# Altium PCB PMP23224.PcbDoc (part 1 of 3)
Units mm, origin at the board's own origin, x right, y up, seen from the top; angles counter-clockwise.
Board outline 180 x 75 mm, 4 copper layers (Top Layer, Signal Layer 1, Signal Layer 2, Bottom Layer), stack 1.565 mm thick; 189 components, 98 nets, 443 pads, 89 vias.
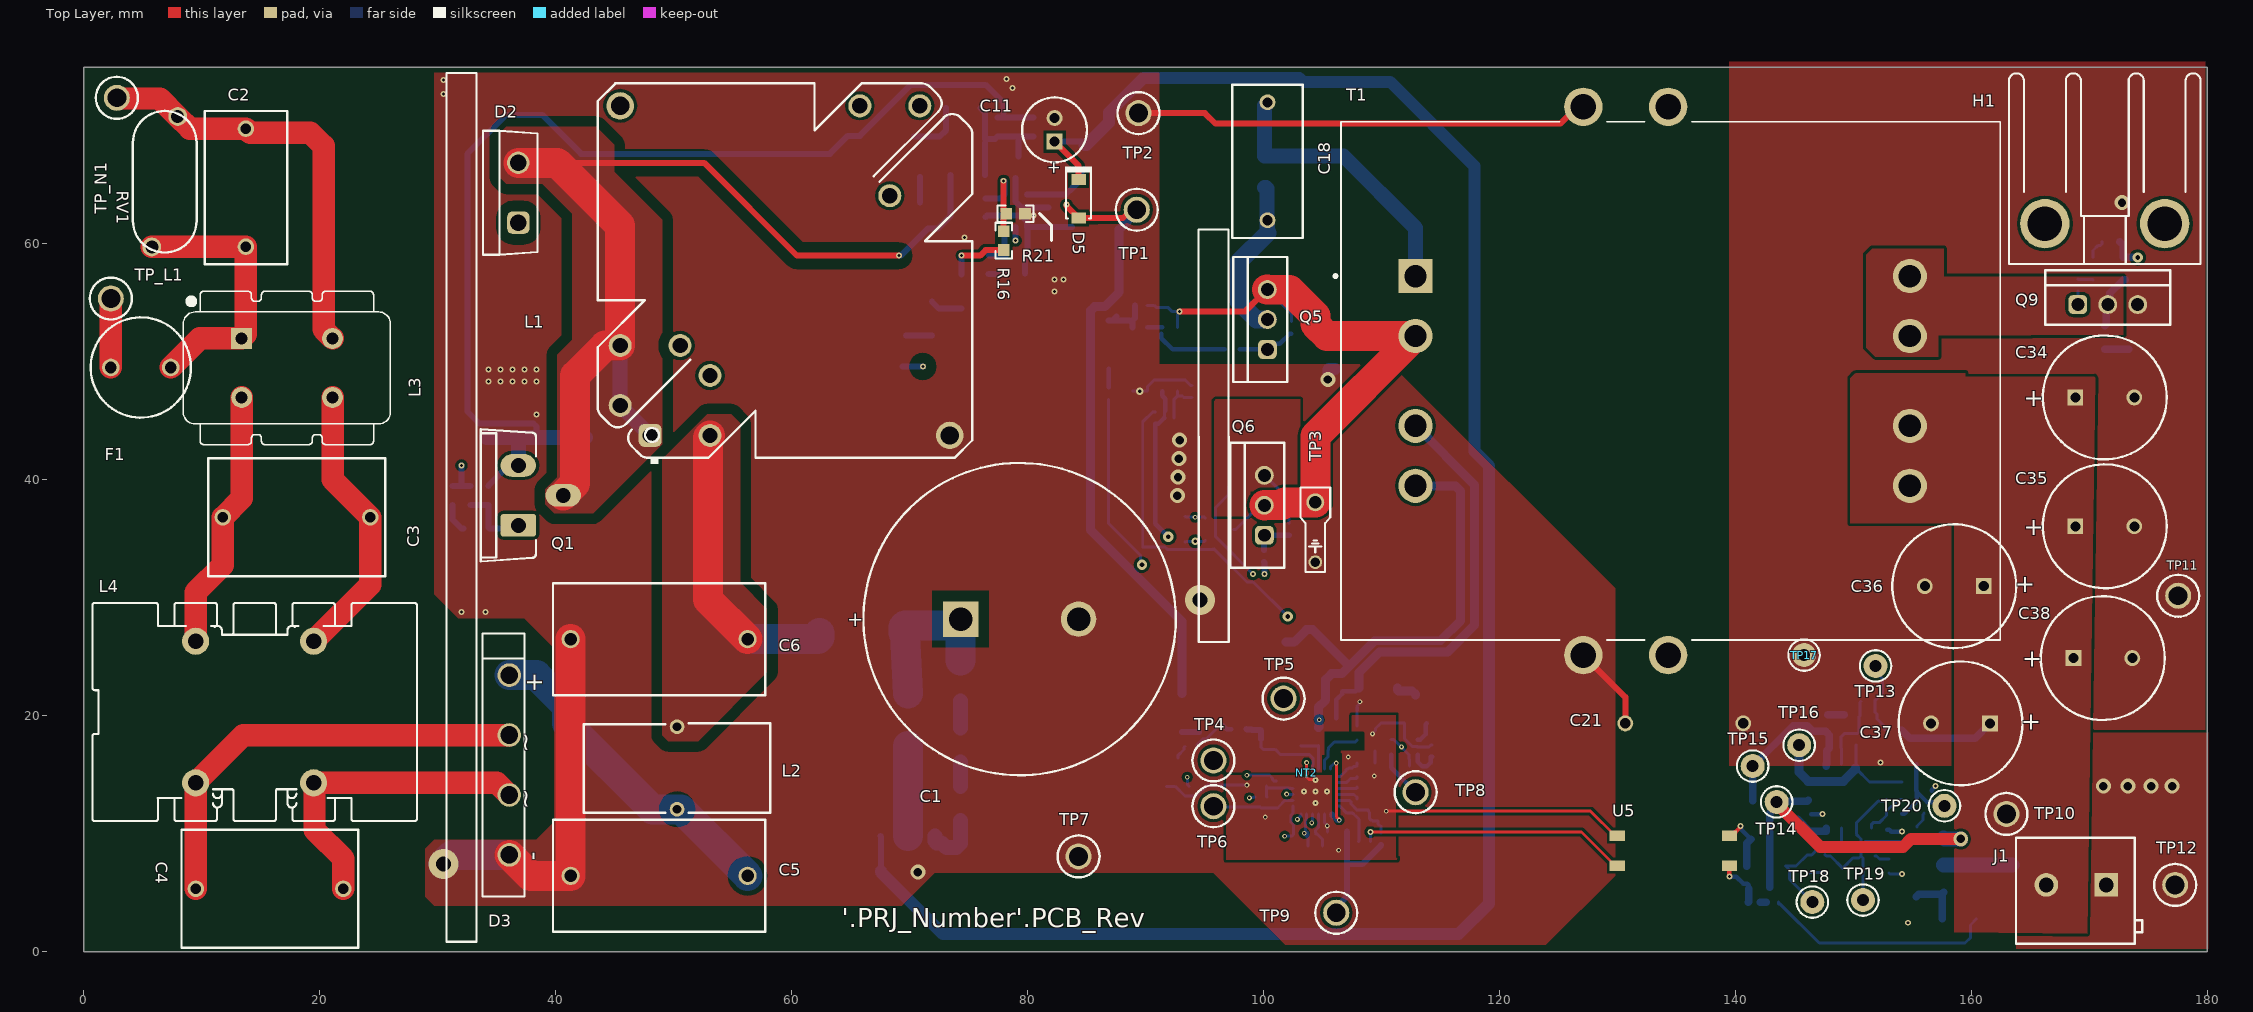
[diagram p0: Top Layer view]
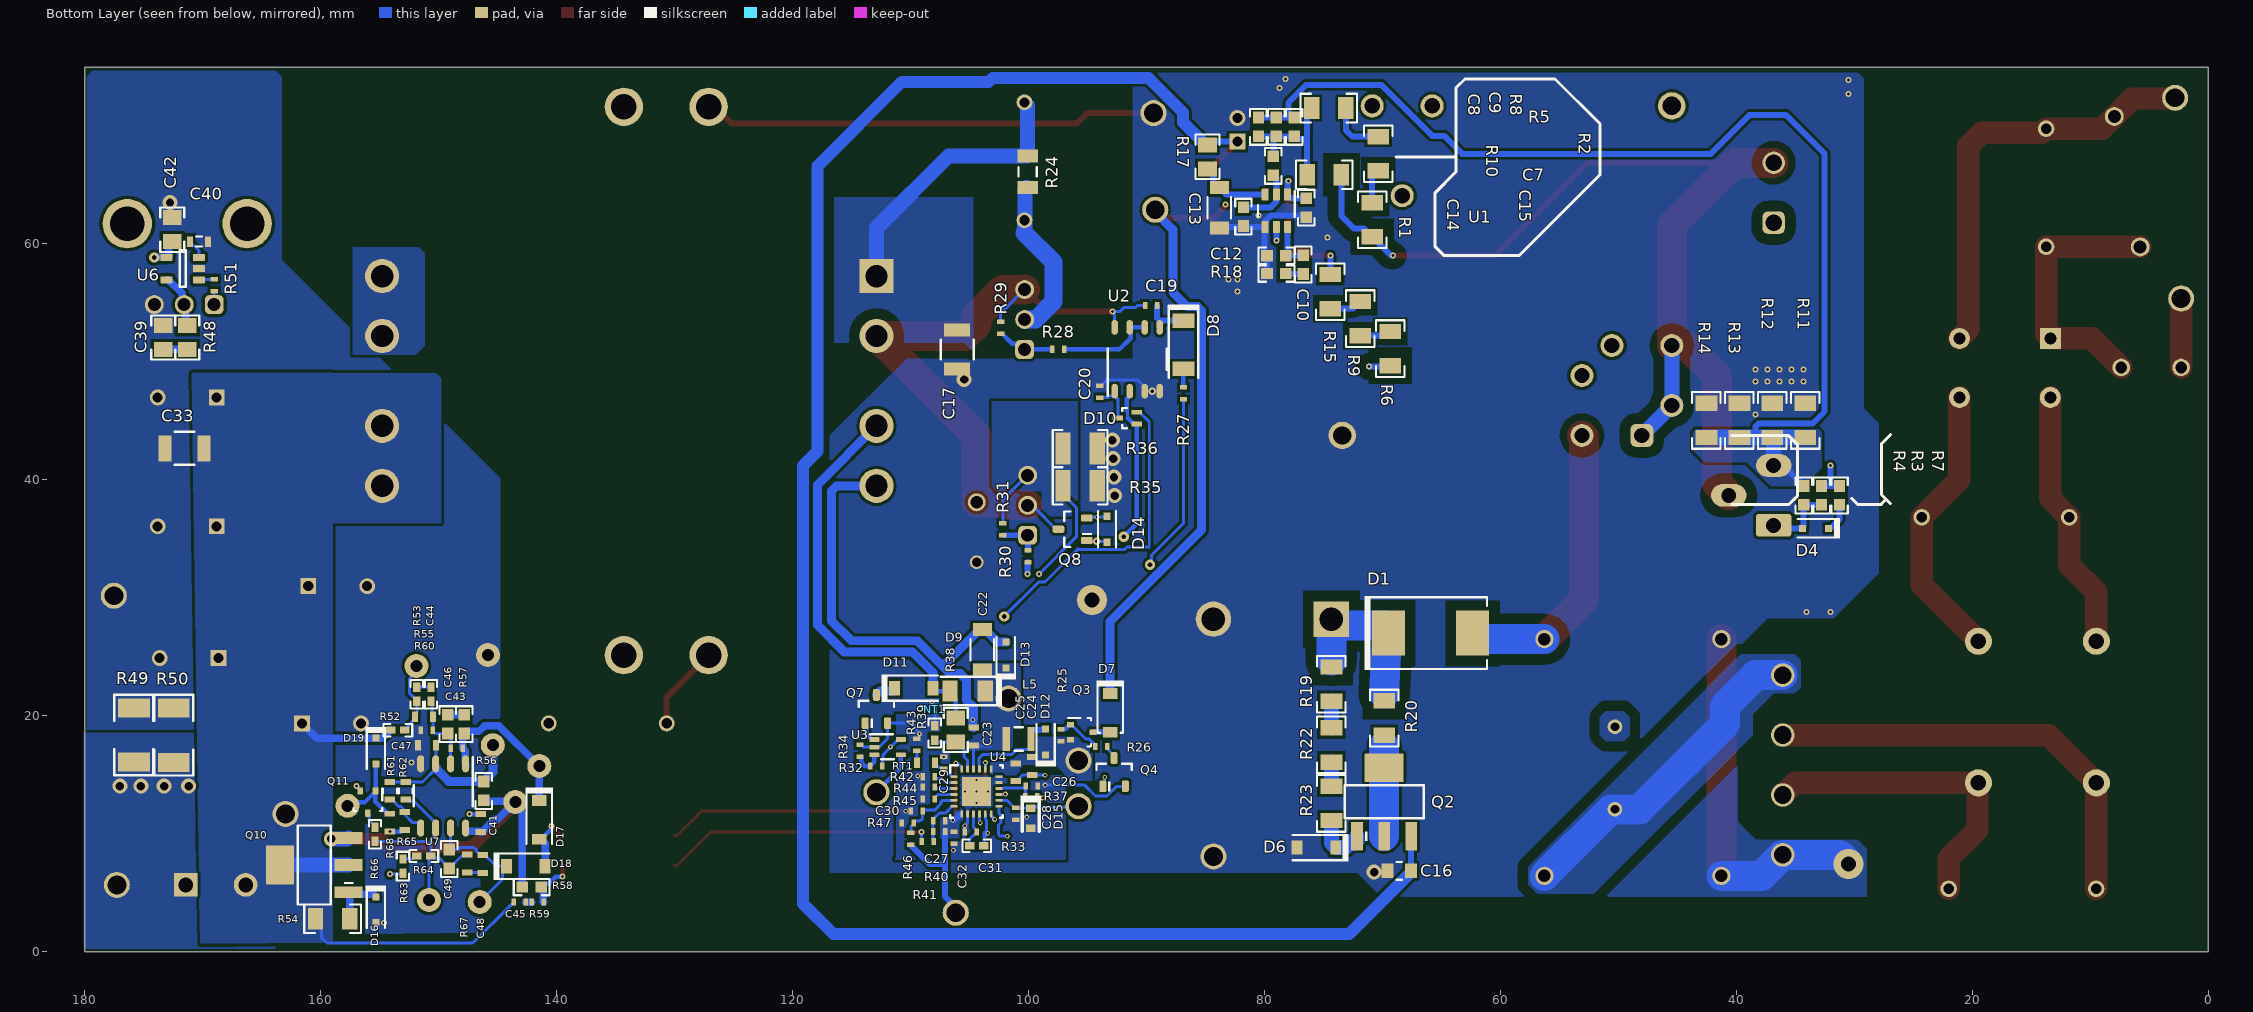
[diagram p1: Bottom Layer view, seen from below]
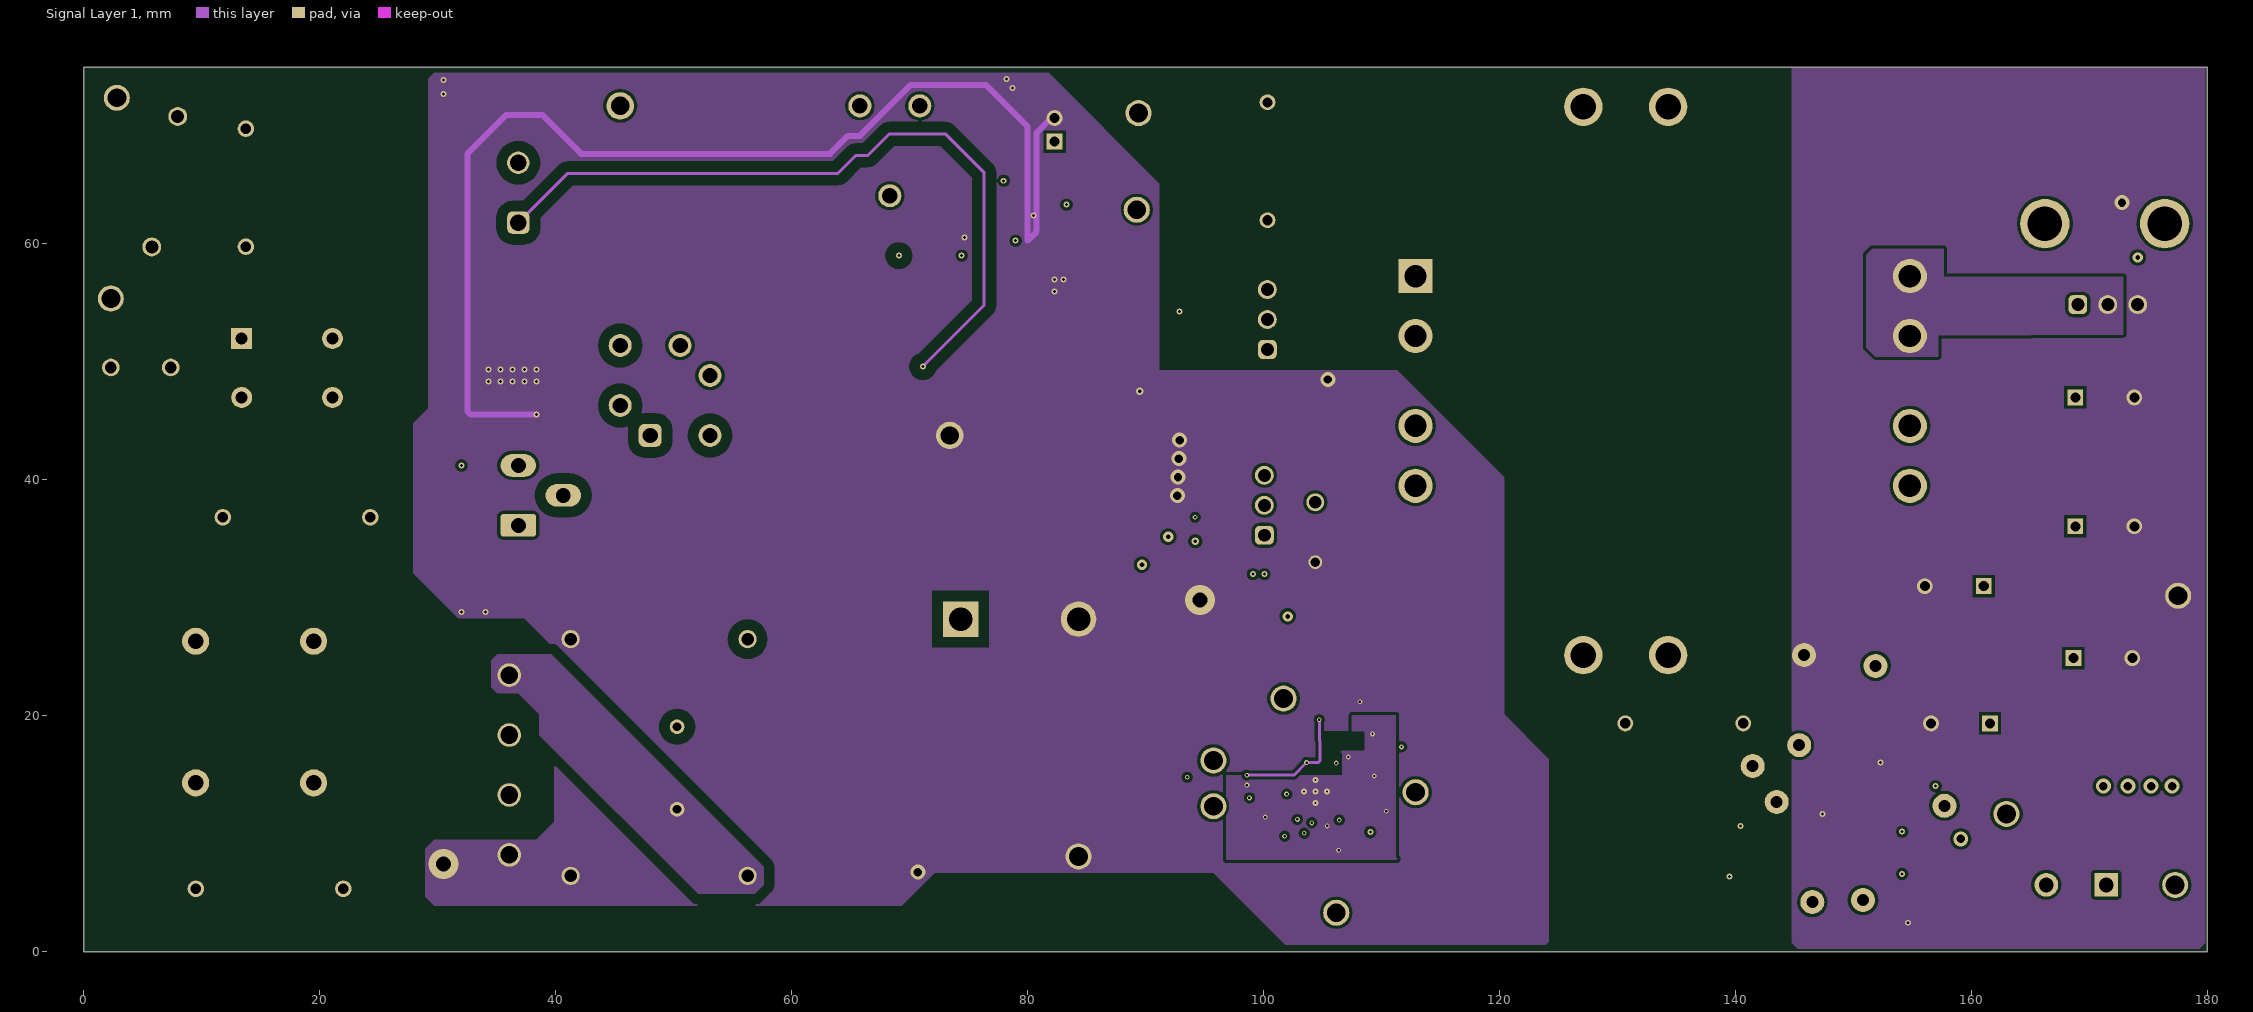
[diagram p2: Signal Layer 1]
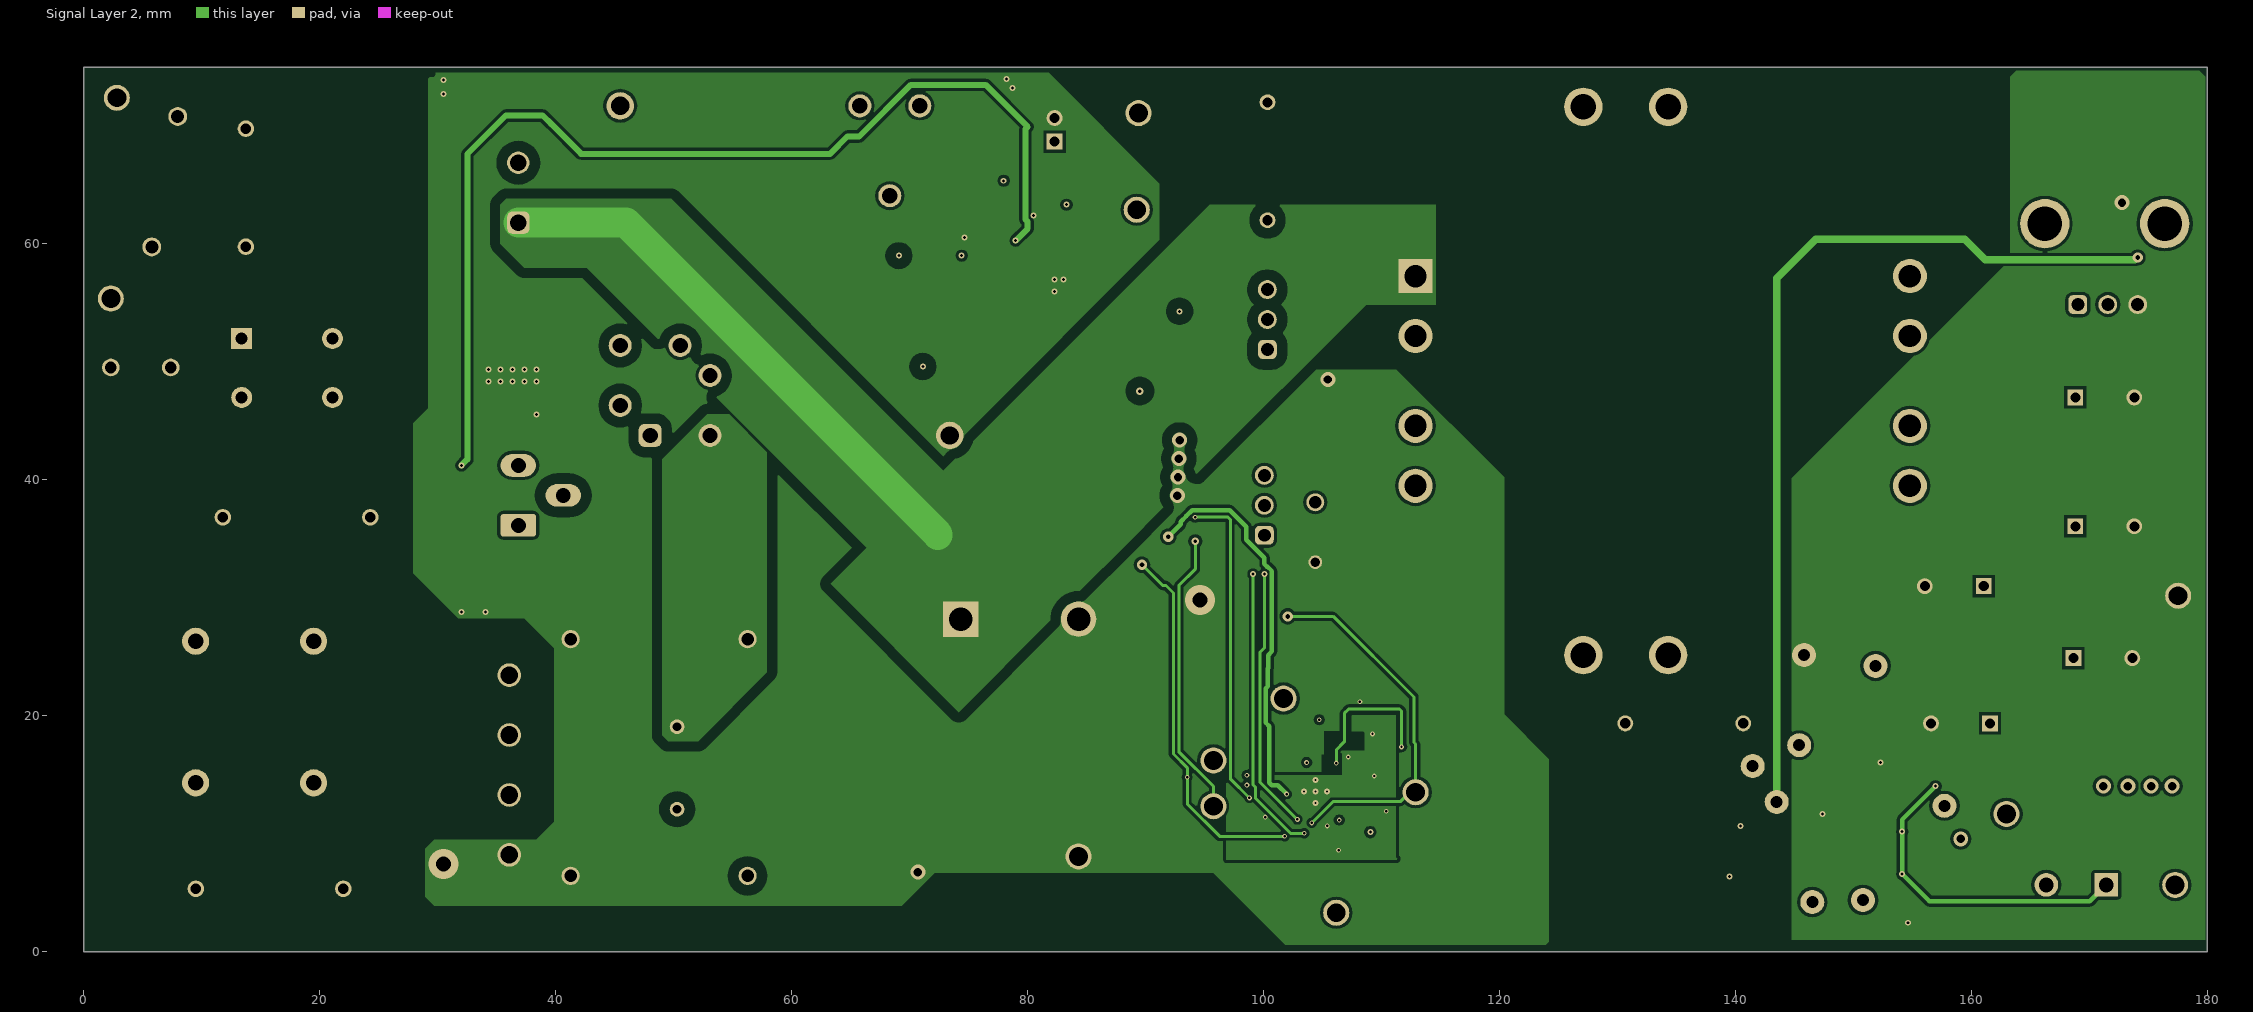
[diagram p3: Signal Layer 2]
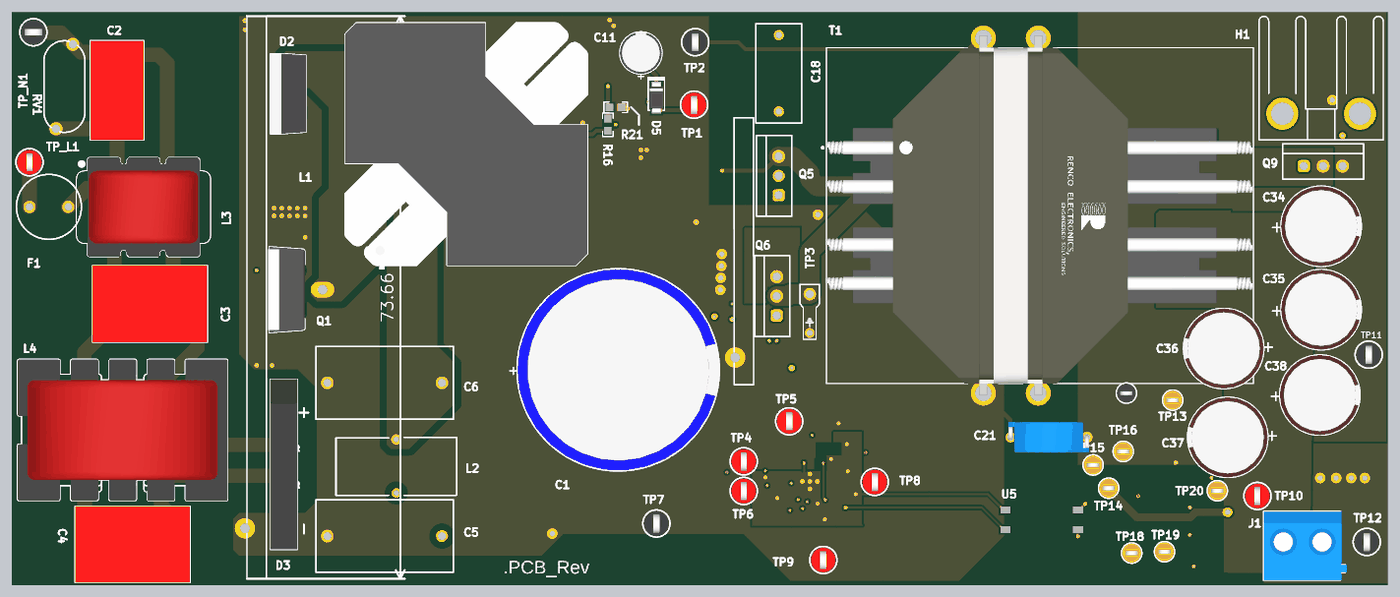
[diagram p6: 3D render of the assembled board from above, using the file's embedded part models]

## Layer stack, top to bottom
Top Solder: solder mask 0.0102, Solder Resist, Dk 3.5
Top Layer: signal copper 0.0356
Dielectric 2: prepreg 0.2032, Dk 4.2
Signal Layer 1: signal copper 0.0356
Dielectric1: core 1.016, FR-4, Dk 4.8
Signal Layer 2: signal copper 0.0356
Dielectric 3: prepreg 0.2032, Dk 4.2
Bottom Layer: signal copper 0.0356
Bottom Solder: solder mask 0.0102, Solder Resist, Dk 3.5

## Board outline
0,0 180,0 180,75 0,75

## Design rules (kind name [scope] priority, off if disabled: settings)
AcuteAngle [All] p1: minimum=4.50000000000000E+0001 checktracksonly=FALSE
AssemblyTestPointUsage [All] p1: valid=2
Clearance Clearance_2 [InNetClass('HV') vs Not InNetClass('HV')] p1: gap=0.889 ignorepadtopadclearanceinfootprint=FALSE
Clearance Clearance_1 [InNetClass('MV') vs Not InNetClass('MV')] p2: gap=0.508 ignorepadtopadclearanceinfootprint=FALSE
Clearance Clearance_Keepouts [((IsTrack Or IsArc) And Not InPoly) And IsFree and IsKeepOut vs ((IsTrack Or IsArc) And Not InPoly) And IsFree and IsKeepOut] p3: gap=0 ignorepadtopadclearanceinfootprint=FALSE
Clearance Clearance_BoardEdge_MountingHoles [OnCopper and InComponentClass('Mounting Holes') vs IsKeepOut] p4: gap=1.016 ignorepadtopadclearanceinfootprint=FALSE except(0: Arc-Hole Track-Hole SMDPad-Hole THPad-Hole Via-Hole Fill-Hole Poly-Hole Region-Hole Text-Hole)
Clearance Clearance_BoardEdge_Poly [OnCopper and InPoly vs IsKeepOut] p5: gap=0.635 ignorepadtopadclearanceinfootprint=FALSE except(0: Arc-Hole Track-Hole SMDPad-Hole THPad-Hole Via-Hole Fill-Hole Poly-Hole Region-Hole Text-Hole)
Clearance Clearance_BoardEdge [OnCopper and Not InComponentClass('Logo') and not InComponentClass('FiducialMark') and not InRegion(1000,500,4000,800) and Not IsKeepout vs IsKeepOut] p6: gap=1.905 ignorepadtopadclearanceinfootprint=FALSE except(0: Arc-Hole Track-Hole SMDPad-Hole THPad-Hole Via-Hole Fill-Hole Poly-Hole Region-Hole Text-Hole)
Clearance Clearance_Poly [InPolygon] p7: gap=0.254 ignorepadtopadclearanceinfootprint=FALSE
Clearance [All] p8: gap=0.2 ignorepadtopadclearanceinfootprint=FALSE except(0: Arc-Hole Track-Hole SMDPad-Hole THPad-Hole Via-Hole Fill-Hole Poly-Hole Region-Hole Text-Hole)
ComponentClearance ComponentClearance_MountingHoles_FiducialMarks [InComponentClass('Mounting Holes') vs InComponentClass('FiducialMark')] p1: gap=0.254 collisioncheckmode=3 verticalgap=0.254 showdistances=FALSE
ComponentClearance ComponentClearance_Shunt [InComponentClass('Header') vs InComponentClass('Shunt')] p2: gap=0 collisioncheckmode=3 verticalgap=0 showdistances=FALSE
ComponentClearance ComponentClearance_Logo [InComponentClass('Logo')] p3: gap=0.127 collisioncheckmode=3 verticalgap=0.254 showdistances=FALSE
ComponentClearance ComponentClearance_ScrewToNut [(HasFootprint('NY PMS 440 0025 PH')) vs (HasFootprint('Keystone_1902C'))] p4: gap=0.508 collisioncheckmode=3 verticalgap=2540 showdistances=FALSE
ComponentClearance ComponentClearance_MountingHoles [InComponentClass('Mounting Holes')] p5: gap=0.508 collisioncheckmode=3 verticalgap=0.254 showdistances=FALSE
ComponentClearance ComponentClearance_SmallPassives [HasFootprint('0201*') or HasFootprint('0402*') or HasFootprint('0508') or HasFootprint('0603*') or HasFootprint('0612') or HasFootprint('0805*') or HasFootprint('0815*') or HasFootprint('0830*') or HasFootprint('1206*') or HasFootprint('1210*') or HasFootprint('1808*') or HasFootprint('1812*') or HasFootprint('1825*') or HasFootprint('2010*') or HasFootprint('2220*') or HasFootprint('2225*') or HasFootprint('2512*') or HasFootprint('2728*') or HasFootprint('3518*') vs HasFootprint('0201*') or HasFootprint('0402*') or HasFootprint('0508') or HasFootprint('0603*') or HasFootprint('0612') or HasFootprint('0805*') or HasFootprint('0815*') or HasFootprint('0830*') or HasFootprint('1206*') or HasFootprint('1210*') or HasFootprint('1808*') or HasFootprint('1812*') or HasFootprint('1825*') or HasFootprint('2010*') or HasFootprint('2220*') or HasFootprint('2225*') or HasFootprint('2512*') or HasFootprint('2728*') or HasFootprint('3518*')] p6: gap=0.254 collisioncheckmode=3 verticalgap=0.254 showdistances=FALSE
ComponentClearance ComponentClearance_THtoSMT [IsThruComponent vs IsSMTComponent] p7: gap=0.254 collisioncheckmode=3 verticalgap=0.254 showdistances=FALSE
ComponentClearance ComponentClearance_THtoTH [IsThruComponent vs IsThruComponent] p8: gap=0.254 collisioncheckmode=3 verticalgap=0.254 showdistances=FALSE
ComponentClearance [All] p9: gap=0.254 collisioncheckmode=3 verticalgap=0.254 showdistances=FALSE
DiffPairsRouting [All] p1: maxlimit=2.54 minlimit=0.254 mostfreqgap=0.254 toplayer_minwidth=0.381 toplayer_maxwidth=0.381 toplayer_prefwidth=0.381 midlayer1_minwidth=0.381 midlayer1_maxwidth=0.381 midlayer1_prefwidth=0.381 midlayer2_minwidth=0.381 midlayer2_maxwidth=0.381 midlayer2_prefwidth=0.381 bottomlayer_minwidth=0.381 bottomlayer_maxwidth=0.381 bottomlayer_prefwidth=0.381 maxuncoupledlength=25.4
FabricationTestPointUsage TestPointUsage [All] p1: valid=2 allowmultiple=FALSE
FabricationTestpoint Testpoint [All] p1: side=3 testpointundercomponent=TRUE minsize=1.016 maxsize=2.54 preferedsize=1.524 minholesize=0 maxholesize=1.016 preferedholesize=0.813 testpointgrid=0.025 allowsidetop=TRUE allowsidebottom=TRUE usegrid=TRUE gridtolerance=0
FanoutControl Fanout_LCC [IsLCC] p1: bgadir=Out bgaviamode=Centered fanoutstyle=Auto fanoutdirection=Alternating viagrid=0.025 // Fanout_LCC (Default Rule)
FanoutControl Fanout_BGA [IsBGA] p2: bgadir=Out bgaviamode=Centered fanoutstyle=Auto fanoutdirection=Alternating viagrid=0.025 // Fanout_BGA (Default Rule)
FanoutControl Fanout_Default [All] p4: bgadir=Out bgaviamode=Centered fanoutstyle=Auto fanoutdirection=Alternating viagrid=0.025 // Fanout_Default (Default Rule)
FanoutControl Fanout_Small [(CompPinCount < 5)] p5: bgadir=Out bgaviamode=Centered fanoutstyle=Auto fanoutdirection=OutThenIn viagrid=0.025 // Fanout_Small (Default Rule)
Height [All] p1: minheight=0 maxheight=76.2 prefheight=12.7
HoleSize [All] p1: absolutevalues=TRUE maxlimit=6.375 minlimit=0.178 maxpercent=80.000 minpercent=20.000
MinimumAnnularRing MinimumAnnularRing_ThermalPadVias [IsVia and InAnyComponent] p1: minimumring=0.102
MinimumAnnularRing [All] p2: minimumring=0.102
MinimumSolderMaskSliver MinimumSolderMaskSliver_Logo [InComponentClass('Logo') vs InComponentClass('Logo')] p1: minsoldermaskwidth=0.018
MinimumSolderMaskSliver [All] p2: minsoldermaskwidth=0.051
PlaneClearance [All] p1: clearance=0.254
PlaneConnect [All] p1: planeconnectstyle=Direct reliefexpansion=0.254 reliefentries=4 reliefconductorwidth=0.254 reliefairgap=0.254
PolygonConnect PolygonConnect_18 [All vs IsNamedPolygon('GND') Or  IsNamedPolygon('C201_2') Or  IsNamedPolygon('HV') Or  IsNamedPolygon('HV') Or  IsNamedPolygon('VD_SR2') Or  IsNamedPolygon('VD_SR2') Or  IsNamedPolygon('Vout') Or  IsNamedPolygon('VD_SR1') Or  IsNamedPolygon('VD_SR2') Or  IsNamedPolygon('VD_SR1') Or  IsNamedPolygon('sGND') Or  IsNamedPolygon('GND') Or  IsNamedPolygon('sGND') Or  IsNamedPolygon('sGND') Or  IsNamedPolygon('VD_SR1') Or  IsNamedPolygon('VD_SR1') Or  IsNamedPolygon('VD_SR2') Or  IsNamedPolygon('IN+') Or  IsNamedPolygon('IN+') Or  IsNamedPolygon('sGND') Or  IsNamedPolygon('C103_2') Or  IsNamedPolygon('C114_2') Or  IsNamedPolygon('HV') Or  IsNamedPolygon('GND') Or  IsNamedPolygon('GND') Or  IsNamedPolygon('GND') Or  IsNamedPolygon('GND') Or  IsNamedPolygon('HV') Or  IsNamedPolygon('HS') Or  IsNamedPolygon('HV') Or  IsNamedPolygon('HV') Or  IsNamedPolygon('C108_1') Or  IsNamedPolygon('Vout') Or  IsNamedPolygon('IN+') Or  IsNamedPolygon('IN+') Or  IsNamedPolygon('C108_1') Or  IsNamedPolygon('GND') Or  IsNamedPolygon('C108_1') Or  IsNamedPolygon('C107_1') Or  IsNamedPolygon('C107_1') Or  IsNamedPolygon('VD') Or  IsNamedPolygon('HV') Or  IsNamedPolygon('GND')] p1: connectstyle=Direct reliefconductorwidth=0.254 reliefentries=4 polygonreliefangle="90 Angle" airgapwidth=0.254
PolygonConnect PolygonConnect_17 [All vs IsNamedPolygon('C103_2') Or  IsNamedPolygon('GND') Or  IsNamedPolygon('GND') Or  IsNamedPolygon('HV') Or  IsNamedPolygon('sGND') Or  IsNamedPolygon('C114_2') Or  IsNamedPolygon('sGND') Or  IsNamedPolygon('IN+') Or  IsNamedPolygon('VD_SR2') Or  IsNamedPolygon('GND') Or  IsNamedPolygon('VD_SR1') Or  IsNamedPolygon('IN+') Or  IsNamedPolygon('VD_SR1') Or  IsNamedPolygon('HS') Or  IsNamedPolygon('IN+') Or  IsNamedPolygon('HV') Or  IsNamedPolygon('IN+') Or  IsNamedPolygon('sGND') Or  IsNamedPolygon('VD_SR2') Or  IsNamedPolygon('HV') Or  IsNamedPolygon('HV') Or  IsNamedPolygon('C201_2') Or  IsNamedPolygon('HV') Or  IsNamedPolygon('VD_SR1') Or  IsNamedPolygon('VD_SR2') Or  IsNamedPolygon('VD_SR1') Or  IsNamedPolygon('sGND') Or  IsNamedPolygon('HV') Or  IsNamedPolygon('Vout') Or  IsNamedPolygon('Vout') Or  IsNamedPolygon('VD_SR2')] p2: connectstyle=Direct reliefconductorwidth=0.254 reliefentries=4 polygonreliefangle="90 Angle" airgapwidth=0.254
PolygonConnect PolygonConnect_16 [All vs IsNamedPolygon('VD_SR2') Or  IsNamedPolygon('VD_SR1')] p3: connectstyle=Direct reliefconductorwidth=0.254 reliefentries=4 polygonreliefangle="90 Angle" airgapwidth=0.254
PolygonConnect PolygonConnect_15 [All vs IsNamedPolygon('C109_2') Or  IsNamedPolygon('C107_2') Or  IsNamedPolygon('HV') Or  IsNamedPolygon('Q203_5') Or  IsNamedPolygon('C107_2') Or  IsNamedPolygon('HS') Or  IsNamedPolygon('Q201_5') Or  IsNamedPolygon('Q203_5') Or  IsNamedPolygon('C106_2') Or  IsNamedPolygon('C108_2') Or  IsNamedPolygon('Vout') Or  IsNamedPolygon('Q203_5') Or  IsNamedPolygon('C108_2') Or  IsNamedPolygon('C113_2') Or  IsNamedPolygon('Q203_5') Or  IsNamedPolygon('Q201_5') Or  IsNamedPolygon('C107_2') Or  IsNamedPolygon('C102_1') Or  IsNamedPolygon('SGND') Or  IsNamedPolygon('GND') Or  IsNamedPolygon('SGND') Or  IsNamedPolygon('GND') Or  IsNamedPolygon('IN+') Or  IsNamedPolygon('IN+') Or  IsNamedPolygon('Q201_5') Or  IsNamedPolygon('Q201_5') Or  IsNamedPolygon('SGND') Or  IsNamedPolygon('SGND') Or  IsNamedPolygon('Vout') Or  IsNamedPolygon('Vout') Or  IsNamedPolygon('IN+') Or  IsNamedPolygon('GND') Or  IsNamedPolygon('IN+') Or  IsNamedPolygon('GND')] p4: connectstyle=Direct reliefconductorwidth=0.254 reliefentries=4 polygonreliefangle="90 Angle" airgapwidth=0.254
PolygonConnect PolygonConnect_14 [All vs IsNamedPolygon('C106_2') Or  IsNamedPolygon('C107_2') Or  IsNamedPolygon('C107_2') Or  IsNamedPolygon('C107_2') Or  IsNamedPolygon('C102_1') Or  IsNamedPolygon('Q203_5') Or  IsNamedPolygon('Vout') Or  IsNamedPolygon('Q203_5') Or  IsNamedPolygon('Q203_5') Or  IsNamedPolygon('Q201_5') Or  IsNamedPolygon('C108_2') Or  IsNamedPolygon('Q203_5') Or  IsNamedPolygon('HS') Or  IsNamedPolygon('HV') Or  IsNamedPolygon('C108_2') Or  IsNamedPolygon('Q201_5') Or  IsNamedPolygon('C109_2') Or  IsNamedPolygon('Q201_5') Or  IsNamedPolygon('Q201_5') Or  IsNamedPolygon('C113_2')] p5: connectstyle=Direct reliefconductorwidth=0.254 reliefentries=4 polygonreliefangle="90 Angle" airgapwidth=0.254
PolygonConnect PolygonConnect_13 [All vs IsNamedPolygon('C102_1') Or  IsNamedPolygon('HV') Or  IsNamedPolygon('C107_2') Or  IsNamedPolygon('C109_2') Or  IsNamedPolygon('C107_2') Or  IsNamedPolygon('C108_2') Or  IsNamedPolygon('C106_2') Or  IsNamedPolygon('C108_2') Or  IsNamedPolygon('C113_2') Or  IsNamedPolygon('C107_2')] p6: connectstyle=Direct reliefconductorwidth=0.254 reliefentries=4 polygonreliefangle="90 Angle" airgapwidth=0.254
PolygonConnect PolygonConnect_12 [All vs IsNamedPolygon('C107_2') Or  IsNamedPolygon('C113_2') Or  IsNamedPolygon('C106_2') Or  IsNamedPolygon('C107_2') Or  IsNamedPolygon('C107_2') Or  IsNamedPolygon('C102_1')] p7: connectstyle=Direct reliefconductorwidth=0.254 reliefentries=4 polygonreliefangle="90 Angle" airgapwidth=0.254
PolygonConnect PolygonConnect_11 [All vs IsNamedPolygon('C106_2') Or  IsNamedPolygon('C102_1') Or  IsNamedPolygon('C107_2') Or  IsNamedPolygon('C107_2') Or  IsNamedPolygon('C107_2')] p8: connectstyle=Direct reliefconductorwidth=0.254 reliefentries=4 polygonreliefangle="90 Angle" airgapwidth=0.254
PolygonConnect PolygonConnect_10 [All vs IsNamedPolygon('C106_2')] p9: connectstyle=Direct reliefconductorwidth=0.254 reliefentries=4 polygonreliefangle="90 Angle" airgapwidth=0.254
PolygonConnect PolygonConnect_9 [All vs IsNamedPolygon('C11_1') Or  IsNamedPolygon('Vin') Or  IsNamedPolygon('Vin') Or  IsNamedPolygon('5V') Or  IsNamedPolygon('D6_2') Or  IsNamedPolygon('Q3_3') Or  IsNamedPolygon('GND2') Or  IsNamedPolygon('GND2') Or  IsNamedPolygon('GND') Or  IsNamedPolygon('Q3_4') Or  IsNamedPolygon('12V5') Or  IsNamedPolygon('GND') Or  IsNamedPolygon('12V5') Or  IsNamedPolygon('D3_1')] p10: connectstyle=Direct reliefconductorwidth=0.254 reliefentries=4 polygonreliefangle="90 Angle" airgapwidth=0.254
PolygonConnect PolygonConnect_8 [All vs IsNamedPolygon('C11_1') Or  IsNamedPolygon('Vin') Or  IsNamedPolygon('12V5') Or  IsNamedPolygon('Q3_3') Or  IsNamedPolygon('GND2') Or  IsNamedPolygon('GND2') Or  IsNamedPolygon('5V') Or  IsNamedPolygon('Q3_4') Or  IsNamedPolygon('12V5')] p11: connectstyle=Direct reliefconductorwidth=0.254 reliefentries=4 polygonreliefangle="90 Angle" airgapwidth=0.254
PolygonConnect PolygonConnect_7 [All vs IsNamedPolygon('GND2') Or  IsNamedPolygon('GND2') Or  IsNamedPolygon('5V') Or  IsNamedPolygon('12V5') Or  IsNamedPolygon('12V5') Or  IsNamedPolygon('C11_1')] p12: connectstyle=Direct reliefconductorwidth=0.254 reliefentries=4 polygonreliefangle="90 Angle" airgapwidth=0.254
PolygonConnect PolygonConnect_6 [All vs IsNamedPolygon('GND2') Or  IsNamedPolygon('SGND') Or  IsNamedPolygon('GND1') Or  IsNamedPolygon('C901_1') Or  IsNamedPolygon('SGND') Or  IsNamedPolygon('GND2') Or  IsNamedPolygon('GND1')] p13: connectstyle=Direct reliefconductorwidth=0.254 reliefentries=4 polygonreliefangle="90 Angle" airgapwidth=0.254
PolygonConnect PolygonConnect_5 [All vs IsNamedPolygon('GND1') Or  IsNamedPolygon('GND1')] p14: connectstyle=Direct reliefconductorwidth=0.254 reliefentries=4 polygonreliefangle="90 Angle" airgapwidth=0.254
PolygonConnect PolygonConnect_4 [All vs IsNamedPolygon('C21_1') Or  IsNamedPolygon('C5_1') Or  IsNamedPolygon('C12_2') Or  IsNamedPolygon('C2_2') Or  IsNamedPolygon('C13_1') Or  IsNamedPolygon('C28_1') Or  IsNamedPolygon('C6_1') Or  IsNamedPolygon('GND') Or  IsNamedPolygon('GND2') Or  IsNamedPolygon('C14_1') Or  IsNamedPolygon('C13_1') Or  IsNamedPolygon('Q1_3') Or  IsNamedPolygon('C14_1') Or  IsNamedPolygon('C5_1') Or  IsNamedPolygon('GND2') Or  IsNamedPolygon('C28_1') Or  IsNamedPolygon('D5_2') Or  IsNamedPolygon('D6_2') Or  IsNamedPolygon('D2_1') Or  IsNamedPolygon('C12_2') Or  IsNamedPolygon('D2_1') Or  IsNamedPolygon('C4_1') Or  IsNamedPolygon('C4_1') Or  IsNamedPolygon('C2_2') Or  IsNamedPolygon('GND') Or  IsNamedPolygon('C33_1') Or  IsNamedPolygon('C9_1')] p15: connectstyle=Direct reliefconductorwidth=0.254 reliefentries=4 polygonreliefangle="90 Angle" airgapwidth=0.254
PolygonConnect PolygonConnect_3 [All vs IsNamedPolygon('C28_1') Or  IsNamedPolygon('C12_2') Or  IsNamedPolygon('C28_1') Or  IsNamedPolygon('C9_1') Or  IsNamedPolygon('D5_2') Or  IsNamedPolygon('C12_2') Or  IsNamedPolygon('C2_2') Or  IsNamedPolygon('C14_1') Or  IsNamedPolygon('C4_1') Or  IsNamedPolygon('C14_1') Or  IsNamedPolygon('D6_2') Or  IsNamedPolygon('GND2') Or  IsNamedPolygon('Q1_3') Or  IsNamedPolygon('C5_1') Or  IsNamedPolygon('D2_1') Or  IsNamedPolygon('C4_1') Or  IsNamedPolygon('C13_1') Or  IsNamedPolygon('C5_1') Or  IsNamedPolygon('C13_1') Or  IsNamedPolygon('C33_1') Or  IsNamedPolygon('D2_1') Or  IsNamedPolygon('GND') Or  IsNamedPolygon('GND') Or  IsNamedPolygon('GND2') Or  IsNamedPolygon('C2_2') Or  IsNamedPolygon('C6_1') Or  IsNamedPolygon('C21_1')] p16: connectstyle=Direct reliefconductorwidth=0.254 reliefentries=4 polygonreliefangle="90 Angle" airgapwidth=0.254
PolygonConnect PolygonConnect_2 [All vs IsNamedPolygon('C21_1') Or  IsNamedPolygon('C4_1') Or  IsNamedPolygon('D5_2') Or  IsNamedPolygon('C5_1') Or  IsNamedPolygon('C14_1') Or  IsNamedPolygon('C13_1') Or  IsNamedPolygon('C4_1') Or  IsNamedPolygon('C33_1') Or  IsNamedPolygon('C12_2') Or  IsNamedPolygon('D2_1') Or  IsNamedPolygon('C2_2') Or  IsNamedPolygon('C28_1') Or  IsNamedPolygon('C12_2') Or  IsNamedPolygon('D2_1') Or  IsNamedPolygon('C5_1') Or  IsNamedPolygon('Q1_3') Or  IsNamedPolygon('GND') Or  IsNamedPolygon('D6_2') Or  IsNamedPolygon('C6_1') Or  IsNamedPolygon('C2_2') Or  IsNamedPolygon('C14_1') Or  IsNamedPolygon('C28_1') Or  IsNamedPolygon('C13_1') Or  IsNamedPolygon('C9_1') Or  IsNamedPolygon('GND')] p17: connectstyle=Direct reliefconductorwidth=0.254 reliefentries=4 polygonreliefangle="90 Angle" airgapwidth=0.254
PolygonConnect PolygonConnect_1 [All vs IsNamedPolygon('C28_1') Or  IsNamedPolygon('D5_2') Or  IsNamedPolygon('C5_1') Or  IsNamedPolygon('C5_1') Or  IsNamedPolygon('D2_1') Or  IsNamedPolygon('C21_1') Or  IsNamedPolygon('C9_1') Or  IsNamedPolygon('C4_1') Or  IsNamedPolygon('C14_1') Or  IsNamedPolygon('C28_1') Or  IsNamedPolygon('C6_1') Or  IsNamedPolygon('C12_2') Or  IsNamedPolygon('C33_1') Or  IsNamedPolygon('C4_1') Or  IsNamedPolygon('C13_1') Or  IsNamedPolygon('C12_2') Or  IsNamedPolygon('D6_2') Or  IsNamedPolygon('C2_2') Or  IsNamedPolygon('C14_1') Or  IsNamedPolygon('D2_1') Or  IsNamedPolygon('C2_2') Or  IsNamedPolygon('C13_1')] p18: connectstyle=Direct reliefconductorwidth=0.254 reliefentries=4 polygonreliefangle="90 Angle" airgapwidth=0.254
PolygonConnect [All] p19: connectstyle=Direct reliefconductorwidth=0.254 reliefentries=4 polygonreliefangle="90 Angle" airgapwidth=0.254
RoutingVias ThermalPadVias [IsVia and InAnyComponent] p1: holewidth=0.2 width=0.5 viastyle="Through Hole" minholewidth=0.2 minwidth=0.5 maxholewidth=0.33 maxwidth=0.6
RoutingVias [All] p2: holewidth=0.406 width=0.864 viastyle="Through Hole" minholewidth=0.2 minwidth=0.406 maxholewidth=101.6 maxwidth=508
SilkToBoardRegionClearance [Not ((IsComment or IsDesignator) And (Hide <> 'False')) and not InRegion(1000,500,4000,800)] p1:
SilkToSilkClearance SilkToSilkClearance_Pb-FreeLogo [(HasFootprint('Pb-Free_Overlay_Medium') OR HasFootprint('Pb-Free_Overlay_Small')) vs (HasFootprint('Pb-Free_Overlay_Medium') OR HasFootprint('Pb-Free_Overlay_Small'))] p1: silktosilkclearance=0
SilkToSilkClearance [All] p2: silktosilkclearance=0
SilkToSolderMaskClearance "Silk to Solder Mask Opening" [All] p1: minsilkscreentomaskgap=0.025 clearancetoexposedcopper=FALSE
SolderMaskExpansion [All] p1: expansion=0.05 istentingtop=FALSE
Width [All] p1: maxlimit=2.54 minlimit=0.152 preferedwidth=0.254 checkconnectedcopper=TRUE
13 further rules are at their usual default settings.

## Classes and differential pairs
net class VDRN: VDRAIN
net class RTN: VOUT
net class PGND: GND
net class GND_SEC: GND_SEC
component class PMP23224: !PCB100 C1 C2 C3 C4 C5 C6 C7 C8 C9 C10 C11 C12 C13 C14 C15 C16 D1 D2 D3 D4 D5 D6 F1 L1 L2 L3 L4 Q1 Q2 R1 R2 R3 R4 R5 R6 R7 R8 R9 R10 R11 R12 R13 R14 R15 R16 R17 R18 R19 R20 R21 R22 R23 RV1 TP_L1 TP_N1 U1
component class PMP23224_BlankSheet: !PCB1 C17 C18 C19 C20 C21 C22 C23 C24 C25 C26 C27 C28 C29 C30 C31 C32 D7 D8 D9 D10 D11 D12 D13 D14 D15 L5 NT1 NT2 Q3 Q4 Q5 Q6 Q7 Q8 R24 R25 R26 R27 R28 R29 R30 R31 R32 R33 R34 R35 R36 R37 R38 R39 R40 R41 R42 R43 R44 R45 R46 R47 RT1 T1 TP1 TP2 TP3 TP4 TP5 TP6 TP7 TP8 TP9 U2 U3 U4 U5
component class PMP23224_ACF_secondary: C33 C34 C35 C36 C37 C38 C39 C40 C41 C42 C43 C44 C45 C46 C47 C48 C49 D16 D17 D18 D19 H1 J1 Q9 Q10 Q11 R48 R49 R50 R51 R52 R53 R54 R55 R56 R57 R58 R59 R60 R61 R62 R63 R64 R65 R66 R67 R68 TP10 TP11 TP12 TP13 TP14 TP15 TP16 TP17 TP18 TP19 TP20 U6 U7
net class MV: NetR1_1 NetR6_1 NetR9_1
net class HV: HV NetC2_2 NetC3_1 NetC3_2 NetC4_1 NetC4_2 NetC5_1 NetC6_1 VD

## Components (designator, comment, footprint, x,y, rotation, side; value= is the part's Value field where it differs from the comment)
C1 "450MXK150MEFCSN25X25" SMQ_2540x2500 79.328,28.194 r0 top value=150uF
C2 "890324023028CS" WCAP-FTX2_1300x700x1200 13.74,64.77 r270 top value=0.22uF
C3 "890324024005" WCAP-FTX2_1500x1000x1600 18.034,36.83 r180 top value=0.47uF
C4 "890324024005" WCAP-FTX2_1500x1000x1600 15.748,5.334 r180 top value=0.47uF
C5 "450MPK105J" MPK_1800x950 48.768,6.431 r180 top value=1uF
C6 "450MPK105J" MPK_1800x950 48.768,26.497 r180 top value=1uF
C7 "VJ1206A100JXGAT5Z" 1206 74.93,65.867 r0 bottom value=10pF
C8 "GRM188R71E392KA01D" 0603 80.518,69.931 r90 bottom value=3900pF
C9 "06035A561JAT2A" 0603 78.994,69.931 r90 bottom value=560pF
C10 "885012206048" 0603 76.708,58.247 r270 bottom value=0.22uF
C11 "ECA-1HHG100" NHG_500x1100 82.296,69.677 r90 top value=10uF
C12 "C1608X5R1H683K080AA" 0603 78.994,59.009 r0 bottom value=0.068uF
C13 "CGA5L2X7R1H474K160AA" 1206_180 83.82,63.073 r270 bottom value=0.47uF
C14 "0603ZC100KAT2A" 0603 81.788,62.311 r270 bottom value=10pF
C15 "06031C102KAT2A" 0603 76.454,63.073 r270 bottom value=1000pF
C16 "C0805C105K3RACTU" 0805_HV1 68.575,6.858 r0 bottom value=1uF
C17 "C1210C104KBRAC7800" 1210_280 106.053,51.054 r270 bottom value=0.1uF
C18 "B32521C3474K" CAPRR1000W60L1300T600H1200 100.345,67.011 r270 top value=0.47uF
C19 "GRM155R71E473KA88D" 0402S 89.613,54.795 r0 bottom value=0.047uF
C20 "GRM155R71E103KA01D" 0402S 93.964,47.479 r90 bottom value=0.01uF
C21 "DE1E3RA222MN4AN01F" DE1_900x400 135.676,19.358 r180 top value=2200pF
C22 "C3216X5R1E336M160AC" 1206_180 103.914,25.604 r90 bottom value=33uF
C23 "GRM188R6YA106MA73" 0603S 104.664,18.242 r90 bottom value=10uF
C24 "C1608X5R1E685K080AC" 0603S 99.678,15.748 r270 bottom value=6.8uF
C25 "GRM188R6YA106MA73" 0603S 101.092,15.214 r270 bottom value=10uF
C26 "GRM1555C1H240JA01D" 0402S 99.738,14.04 r180 bottom value=24pF
C27 "GRM155R71H331KA01D" 0402S 107.583,11.11 r180 bottom value=330pF
C28 "GRM155R61E105KA12D" 0402S 101.092,11.684 r270 bottom value=1uF
C29 "GRM1555C1H101JA01D" 0402S 107.188,16.002 r90 bottom value=100pF
C30 "GRM1555C1H101JA01D" 0402S 109.474,11.938 r0 bottom value=100pF
C31 "GRM1555C1H101JA01D" 0402S 104.902,10.16 r180 bottom value=100pF
C32 "GRM155R71C224KA12D" 0402S 106.314,9.652 r270 bottom value=0.22uF
C33 "C3225X5R1H106K250AB" 1210_280 171.539,42.672 r0 bottom value=10uF
C34 "ELXZ250ELL471MJ16S" Chemi-Con_1000x1600 171.323,46.99 r0 top value=470uF
C35 "ELXZ250ELL471MJ16S" Chemi-Con_1000x1600 171.323,36.068 r0 top value=470uF
C36 "ELXZ250ELL471MJ16S" Chemi-Con_1000x1600 158.564,30.988 r180 top value=470uF
C37 "ELXZ250ELL471MJ16S" Chemi-Con_1000x1600 159.095,19.358 r180 top value=470uF
C38 "ELXZ250ELL471MJ16S" Chemi-Con_1000x1600 171.156,24.892 r0 top value=470uF
C39 "GRM21A5C2E331JW01D" 0805_HV 173.355,52.07 r270 bottom value=330pF
C40 "GRM188C71E225KE11D" 0603S 170.329,60.198 r180 bottom value=2.2uF
C41 "Capacitor" 0603S 146.436,10.906 r270 bottom value=1uF
C42 "C2012X5R1H105K125AB" 0805_HV 172.593,61.214 r90 bottom value=1uF
C43 "GRM1555C1E330JA01D" 0402S 148.468,17.256 r180 bottom value=33pF
C44 "GRM155R71H272KA01D" 0402 150.662,21.828 r270 bottom value=2700pF
C45 "GRM155R71H183KA12D" 0402S 143.134,4.21 r180 bottom value=0.018uF
C46 "GRM188R71C103KA01D" 0603 149.23,19.288 r90 bottom value=0.01uF
C47 "Capacitor" 0603S 151.008,17.51 r0 bottom value=1uF
C48 "Capacitor" 0603S 146.283,7.439 r270 bottom value=1uF
C49 "GRM188R71E103KA01D" 0603 149.103,7.858 r90 bottom value=0.01uF
D1 "RS3K-E3/9AT" SMC 65.925,27.005 r180 bottom value=800V
D2 "STTH8L06FP" TO-220AC 36.83,64.343 r90 top value=600V
D3 "GBU8J-BP" GBU 36.068,15.829 r270 top value=420V
D4 "MMDL914-TP" SOD-323 33.274,35.895 r0 bottom value=100V
D5 "1N4148WFL-G3-08" SOD-123FL 84.328,63.835 r270 top value=100V
D6 "DDZ16-7" SOD-123 75.603,8.832 r0 bottom value=16V
D7 "1N4148WFL-G3-08" SOD-123FL 93.075,20.243 r270 bottom value=100V
D8 "ES1JAF" SMAF 86.868,51.454 r270 bottom value=600V
D9 "CSFMT108-HF" SOD-123H 105.164,22.098 r0 bottom value=600V
D10 "BAT54CT-7-F" SOT-523 91.634,45.239 r0 bottom value=30V
D11 "BAV21W-7-F" SOD-123 109.728,22.352 r180 bottom value=200V
D12 "CUS08F30,H3F" SOD-323 98.552,17.78 r90 bottom value=30V
D13 "CDSOD323-T24S" SOD-323 101.926,25.146 r90 bottom value=24V
D14 "CDSOD323-T18C" SOD-323-Bi 93.345,35.814 r90 bottom value=18V
D15 "CZRU52C20" SOD-523F 99.822,11.316 r270 bottom value=20V
D16 "MMSZ5232BS-7-F" SOD-323 155.326,3.556 r270 bottom value=5.6V
D17 "MMSD914T1G" SOD-123 141.478,11.176 r270 bottom value=100V
D18 "MMSD914T1G" SOD-123 142.626,7.258 r180 bottom value=100V
D19 "MMSZ5240BS-7-F" SOD-323 155.326,17.002 r270 bottom value=10V
F1 "37215000001" FUSE_372 4.826,49.53 r0 top
H1 "634-20ABP" HSINK_634-10ABP 171.323,61.722 r0 top
J1 "ED120/2DS" On-Shore_ED120_2DS 168.91,5.665 r180 top
L1 "750317259" 750317259 59.436,57.739 r90 top value=120uH
L2 "7447021" IND_7447020 50.292,15.575 r90 top value=100µH
L3 "744822301" IND_WE-CMB-S 17.232,49.49 r270 top value=1mH
L4 "744824310" IND_WE-CMB_L 14.478,20.32 r0 top value=10mH
L5 "BRC2518T220K" 1007 100.838,18.034 r0 bottom value=22uH
NT1 "Net-Tie" Net-Tie_10mil 107.95,20.574 r90 bottom net-tie
NT2 "Net-Tie" Net-Tie_10mil 103.657,15.162 r90 top net-tie
Q1 "IPP60R099C7" TO-220AB 36.83,38.689 r90 top value=600V
Q2 "STN1NK60Z" SOT-223 69.85,12.7 r90 bottom value=600V
Q3 "BSS84W-7-F" SOT-323 95.491,18.606 r180 bottom value=-50V
Q4 "2N7002Q-7-F" SOT-23 92.745,15.221 r90 bottom value=60V
Q5 "IPA70R360P7" TO-220-3 100.33,53.594 r90 top value=700V
Q6 "IPA70R360P7" TO-220-3 100.076,37.846 r90 top value=700V
Q7 "BSS123" SOT-23 112.903,20.574 r90 bottom value=100V
Q8 "BSS126H6327XTSA2" SOT-23 96.266,35.814 r0 bottom value=600V
Q9 "IPP110N20N3G" TO-220-3 171.577,54.864 r0 top value=200V
Q10 "FZT493TA" SOT-223 160.554,7.35 r0 bottom value="100 V"
Q11 "2N7002KW" SOT-323 156.013,12.69 r270 bottom value=60V
R1 "CRCW12063M09FKEA" 1206 70.866,62.057 r270 bottom value=3.09Meg
R2 "CRCW12063M30JNEA" 1206 70.358,67.645 r270 bottom value=3.3Meg
R3 "CRCW060310R0FKEA" 0603 32.766,38.689 r270 bottom value=10.0
R4 "CRCW060382K5FKEA" 0603 34.29,38.689 r270 bottom value=82.5k
R5 "CRCW12063M30JNEA" 1206 74.549,71.521 r180 bottom value=3.3Meg
R6 "CRCW12063M09FKEA" 1206 69.342,51.135 r270 bottom value=3.09Meg
R7 "CRCW06031R00FKEA" 0603 31.242,38.689 r270 bottom value=1.00
R8 "CRCW060324K3FKEA" 0603 77.47,69.931 r270 bottom value=24.3k
R9 "CRCW12063M30JNEA" 1206 71.882,53.675 r270 bottom value=3.3Meg
R10 "CRCW06033K00JNEA" 0603 79.248,66.629 r270 bottom value=3.0k
R11 "CSR1206FTR130" 1206 34.152,45.039 r270 bottom value=0.13
R12 "CSR1206FTR130" 1206 36.946,45.039 r270 bottom value=0.13
R13 "ERJ-8BSFR15V" 1206 39.74,45.039 r270 bottom value=0.15
R14 "ERJ-8BSFR15V" 1206 42.534,45.039 r270 bottom value=0.15
R15 "CRCW12063M30JNEA" 1206 74.422,55.961 r270 bottom value=3.3Meg
R16 "CRCW060328K0FKEA" 0603 77.978,60.279 r270 top value=28.0k
R17 "CRCW080510R0FKEA" 0805_HV 84.836,67.391 r90 bottom value=10.0
R18 "CRCW0603140KFKEA" 0603 78.994,57.485 r180 bottom value=140k
R19 "CRCW12063M24FKEA" 1206 74.328,22.687 r90 bottom value=3.24Meg
R20 "CRCW120651K1FKEA" 1206 69.85,19.812 r90 bottom value=51.1k
R21 "CRCW060360K4FKEA" 0603 78.994,62.565 r180 top value=60.4k
R22 "CRCW12063M24FKEA" 1206 74.328,17.526 r90 bottom value=3.24Meg
R23 "CRCW12063M24FKEA" 1206 74.328,12.571 r90 bottom value=3.24Meg
R24 "CRCW12063M30JNEA" 1206L 100.076,66.121 r90 bottom value=3.3Meg
R25 "CRCW0402100KFKED" 0402S 97.255,18.356 r270 bottom value=100k
R26 "CRCW0402100KFKED" 0402S 93.845,17.389 r0 bottom value=100k
R27 "CRCW04024R70JNED" 0402S 86.868,47.325 r90 bottom value=4.7
R28 "CRCW040215R0JNED" 0402S 97.466,51.067 r0 bottom value=15
R29 "CRCW040210K0JNED" 0402S 102.362,52.913 r270 bottom value=10k
R30 "CRCW040215R0JNED" 0402S 100.055,33.528 r90 bottom value=15
R31 "CRCW040210K0JNED" 0402S 102.181,35.814 r270 bottom value=10k
R32 "CRCW0402348KFKED" 0402S 112.903,15.748 r180 bottom value=348k
R33 "CRCW04021K00FKED" 0402 104.394,8.982 r180 bottom value=1.00k
R34 "CRCW0402348KFKED" 0402S 114.3,17.018 r90 bottom value=348k
R35 "ERJ14RSJR18U" 1210 95.631,39.497 r0 bottom value=0.18
R36 "ERJ14RSJR18U" 1210 95.631,42.672 r0 bottom value=0.18
R37 "CRCW0402499RFKED" 0402S 99.778,13.13 r180 bottom value=499
R38 "CRCW080584K5FKEA" 0805_HV 106.172,18.796 r90 bottom value=84.5k
R39 "CRCW040247K5FKED" 0402 107.95,18.542 r270 bottom value=47.5k
R40 "CRCW04021M00JNED" 0402S 107.583,10.186 r180 bottom value=1.0Meg
R41 "CRCW040220K0JNED" 0402S 108.55,9.332 r0 bottom value=20k
R42 "CRCW0402196KFKED" 0402S 108.458,14.834 r180 bottom value=196k
R43 "CRCW04020000Z0ED" 0402S 109.474,17.526 r270 bottom value=0
R44 "CRCW0402196KFKED" 0402S 108.458,13.97 r180 bottom value=196k
R45 "CRCW04020000Z0ED" 0402S 108.458,12.954 r0 bottom value=0
R46 "CRCW0402150KFKED" 0402S 109.982,9.56 r270 bottom value=150k
R47 "CRCW040253K6FKED" 0402S 110.236,10.922 r0 bottom value=53.6k
R48 "RT0805BRD0753R6L" 0805_HV 171.323,52.07 r270 bottom value=53.6
R49 "CSRN2010FT10L0" 2010 175.844,18.375 r270 bottom value=0.01
R50 "CSRN2010FT10L0" 2010 172.466,18.355 r270 bottom value=0.01
R51 "CRCW04020000Z0ED" 0402S 169.037,56.515 r90 bottom value=0
R52 "CRCW040210R0FKED" 0402 153.464,18.78 r0 bottom value=10.0
R53 "CRCW04023K01FKED" 0402 151.862,21.828 r270 bottom value=3.01k
R54 "CRCW120610K0FKEA" 1206 159.004,2.794 r0 bottom value=10.0k
R55 "Resistor" 0603S 151.262,19.923 r0 bottom value=100k
R56 "CRCW06031K00JNEA" 0603 146.182,13.634 r270 bottom value=1.0k
R57 "CRCW060360K4FKEA" 0603 147.833,19.288 r90 bottom value=60.4k
R58 "CRCW06032K00JNEA" 0603 142.118,5.48 r0 bottom value=2.0k
R59 "CRCW0402150RFKED" 0402S 141.61,4.21 r0 bottom value=150
R60 "CRCW040212K7FKED" 0402S 151.008,18.78 r180 bottom value=12.7k
R61 "TNPW060310K0BEEA" TNPW0603 154.145,13.641 r90 bottom value=10.0k
R62 "TNPW060310K0BEEA" TNPW0603 152.803,13.641 r90 bottom value=10.0k
R63 "CRCW0402191RFKED" 0402 153.04,7.258 r270 bottom value=191
R64 "CRCW04029K31FKED" 0402 151.262,8.112 r0 bottom value=9.31k
R65 "RG1608P-9761-B-T5" 0603S 152.878,11.088 r90 bottom value=9.76k
R66 "CRCW0402576KFKED" 0402 155.401,9.964 r270 bottom value=576k
R67 "Resistor" 0603S 147.591,7.482 r270 bottom value=100k
R68 "Resistor" 0603S 154.145,10.934 r90 bottom value=10.0k
RT1 "NCP18WB473J03RB" 0603S 108.712,16.002 r180 bottom value=47k
RV1 "S10K275E2" VAR_S10K275E2 6.858,65.278 r90 top
T1 "RLTI-1439" FP-RLTI-1439_PTH_XFRMR_2IN20_1IN73-MFG 134.518,48.387 r0 top
TP1 "5010" Keystone5010 89.258,62.9 r0 top
TP2 "5011" Keystone5011 89.408,71.089 r0 top
TP3 "TESTPOINT_PIGTAIL" TESTPOINT_PIGTAIL 104.394,38.1 r0 top
TP4 "5010" Keystone5010 95.758,16.216 r0 top
TP5 "5010" Keystone5010 101.707,21.457 r0 top
TP6 "5010" Keystone5010 95.758,12.334 r0 top
TP7 "5011" Keystone5011 84.328,8.079 r0 top
TP8 "5010" Keystone5010 112.903,13.521 r0 top
TP9 "5010" Keystone5010 106.172,3.302 r0 top
TP10 "5010" Keystone5010 162.985,11.684 r0 top
TP11 "5011" Keystone5011 177.546,30.177 r0 top
TP12 "5011" Keystone5011 177.292,5.665 r0 top
TP13 "5003" Keystone5003 151.892,24.229 r90 top
TP14 "5003" Keystone5003 143.51,12.701 r90 top
TP15 "5003" Keystone5003 141.478,15.743 r90 top
TP16 "5003" Keystone5003 145.42,17.51 r90 top
TP17 "5001" Keystone5001 145.835,25.146 r90 top
TP18 "5003" Keystone5003 146.53,4.21 r90 top
TP19 "5003" Keystone5003 150.825,4.381 r90 top
TP20 "5003" Keystone5003 157.734,12.369 r90 top
TP_L1 "5010" Keystone5010 2.286,55.372 r0 top
TP_N1 "TP_N100" Keystone5011 2.794,72.39 r90 top
U1 "UCC28056DBV" DBV0006A_N 78.994,62.819 r270 bottom
U2 "UCC5350SBDR" D0008B_L 90.789,50.227 r90 bottom
U3 "TLV7011DCKR" DCK0005A_N 111.953,17.338 r180 bottom
U4 "UCC28782ADRTW" RTW0024B 104.414,13.584 r180 bottom
U5 "VOL618A-2T" SOP254P1020X230-4 134.752,8.573 r180 top
U6 "UCC24612-2DBVT" DBV0005A_N 171.704,57.912 r0 bottom
U7 "TI-AMP-D6-2-8_D" D0008A_N 149.625,13.208 r270 bottom

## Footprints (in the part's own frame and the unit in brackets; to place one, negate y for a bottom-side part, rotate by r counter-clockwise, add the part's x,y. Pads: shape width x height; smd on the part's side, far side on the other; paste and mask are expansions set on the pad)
0402 [mm] "0402 from SM-752 data"
  rect 0.8x0.6 smd: 1(-0.6,0) 2(0.6,0)
  silkscreen extent -1.22,-0.52 1.22,0.52, body extent -0.55,-0.3 0.55,0.3, height 0.6
0402S [mil] "Based on C0402S footprint from PADS legacy"
  rect 15x24 smd: 1(-20,0) 2(20,0)
  body extent -22,-12 22,12, height 24
0603 [mm] "0603 from SM-752 data"
  rect 1x0.95 smd: 1(-0.8,0) 2(0.8,0)
  silkscreen extent -1.52,-0.69 1.52,0.69, body extent -0.87,-0.47 0.87,0.47, height 1
0603S [mil]
  rect 20x35 smd: 1(-30,0) 2(30,0)
  body extent -34,-19 34,19, height 39
0805_HV [mil] "0805 with 30mil clearance between pads"
  rect 50x63 smd: 1(-40,0) 2(40,0)
  silkscreen extent -74,-40 74,40, body extent -43,-29 43,29, height 57
0805_HV1 [mm] "Custom footprint based on analyzing multiple manufacturer recommendations"
  rrect10% 1x1.25 smd: 1(-1,0) 2(1,0)
  silkscreen extent -0.2,-0.75 0.2,0.75, body extent -1.1,-0.72 1.1,0.73, height 1.45
1007 [mm] "SMD, 2-Leads, Body 2.5x1.8mm"
  rect 0.6x2 smd: 1(-1.05,0) 2(1.05,0)
  silkscreen extent -0.35,-1 0.35,1, body extent -1.35,-1 1.35,1, height 2
1206 [mm] "1206 from SM-752 data"
  rect 1.3x1.85 smd: 1(-1.45,0) 2(1.45,0)
  silkscreen extent -2.4,-1.21 2.4,1.21, body extent -1.7,-0.9 1.7,0.9, height 1.35
1206_180 [mm] "1206_180"
  rect 1.1x1.6 smd: 1(-1.7,0) 2(1.7,0)
  silkscreen extent -0.9,-1 0.9,1, body extent -1.75,-0.95 1.75,0.95, height 1.8
1206L [mm] "1206 from SM-752 data"
  rect 1.1x1.75 smd: 1(-1.35,0) 2(1.35,0)
  silkscreen extent -0.4,-0.77 0.4,0.77, body extent -1.7,-0.9 1.7,0.9, height 1.35
1210 [mm] "1210 from SM-752 data"
  rect 1.3x2.7 smd: 1(-1.45,0) 2(1.45,0)
  silkscreen extent -2.32,-1.57 2.32,1.57, body extent -1.7,-1.35 1.7,1.35, height 1.35
1210_280 [mm] "SMD, 2-Leads, Body 3.6x2.8mm, Height 2.8mm"
  rect 1.1x2.2 smd: 1(-1.65,0) 2(1.65,0)
  silkscreen extent -0.84,-1.4 0.84,1.4, body extent -1.8,-1.4 1.8,1.4, height 2.8
2010 [mm] "Chip Capacitor, Body 5.08x2.54mm, IPC Medium Density"
  rect 1.6x2.7 smd: 1(-2.3,0) 2(2.3,0)
  silkscreen extent -3.42,-1.65 3.42,1.65, body extent -2.73,-1.45 2.73,1.45, height 1.66
750317259 [mm] "SMD, 12-Leads, Body 31.75x31.75mm"
  rrect50% 1.95x1.95 hole 1.3: 1(-13.97,11.43)
  round 1.95 hole 1.3: 2(-13.97,6.35) 3(-8.89,6.35) 4(6.35,-8.89) 7(13.97,-11.43) 8(13.97,-6.35) 10(-6.35,8.89) 11(-6.35,13.97) 12(-11.43,13.97)
  round 2.325 hole 1.55: 13(-13.97,-13.97) 14(13.97,13.97)
  silkscreen extent -16.4,-15.87 15.88,15.88, body extent -15.87,-15.87 15.88,15.88, height 24.64
CAPRR1000W60L1300T600H1200 [mm] "EPCOS"
  round 1.35 hole 0.85: 1(-5,0) 2(5,0)
  silkscreen extent -6.5,-3 6.5,3, body extent -6.5,-3 6.5,3, height 12
Chemi-Con_1000x1600 [mm] "TH, 2-Leads, Dia 10mm, Pin Spacing 5mm"
  rect 1.35x1.35 hole 0.85: 1(-2.5,0)
  round 1.35 hole 0.85: 2(2.5,0)
  silkscreen extent -5.25,-5.25 5.25,5.25, body extent -5.25,-5.25 5.26,5.25, height 17.5
D0008A_N [mm] "SOIC, 8-Leads, Body 4.9x3.9mm, Pitch 1.27mm, IPC Medium Density"
  oval 1.45x0.6 smd: 1(-2.725,1.905) 2(-2.725,0.635) 3(-2.725,-0.635) 4(-2.725,-1.905) 5(2.725,-1.905) 6(2.725,-0.635) 7(2.725,0.635) 8(2.725,1.905)
  silkscreen extent -3.3,-2.5 0.9,2.5, body extent -3,-2.45 3,2.45, height 1.63
D0008B_L [mm] "SOIC, 8-Leads, Body 4.9x3.9mm, Pitch 1.27mm, IPC High Density"
  oval 1.25x0.55 smd: 1(-2.7,1.905) 2(-2.7,0.635) 3(-2.7,-0.635) 4(-2.7,-1.905) 5(2.7,-1.905) 6(2.7,-0.635) 7(2.7,0.635) 8(2.7,1.905)
  silkscreen extent -3.1,-2.5 0.9,2.5, body extent -3,-2.45 3,2.45, height 1.63
DBV0005A_N [mm] "SOT23, 5-Leads, Body 2.9x1.6mm, Pitch 0.95mm, Lead Span 2.8mm, IPC Medium Density"
  rrect17% 1x0.6 smd: 1(-1.375,0.95) 2(-1.375,0) 3(-1.375,-0.95) 4(1.375,-0.95) 5(1.375,0.95)
  silkscreen extent -0.25,-1.55 0.25,1.55, body extent -1.42,-1.46 1.42,1.46, height 1.09
DBV0006A_N [mm] "SOT23, 6-Leads, Body 2.9x1.6mm, Pitch 0.95mm, Lead Span 2.8mm, IPC Medium Density"
  rrect17% 1x0.6 smd: 1(-1.375,0.95) 2(-1.375,0) 3(-1.375,-0.95) 4(1.375,-0.95) 5(1.375,0) 6(1.375,0.95)
  silkscreen extent -1.68,-1.55 0.5,1.55, body extent -1.42,-1.46 1.42,1.46, height 1.12
DCK0005A_N [mm] "SOT353, 5-Leads, Body 2x1.3mm, Pitch 0.65mm, Lead Span 2.1mm, IPC Medium Density"
  rrect25% 0.85x0.4 smd: 1(-1.125,0.65) 2(-1.125,0) 3(-1.125,-0.65) 4(1.125,-0.65) 5(1.125,0.65)
  silkscreen extent -1.48,-1.02 0.55,1.1, body extent -1.14,-1 1.14,1, height 0.95
DE1_900x400 [mm] "TH, 2-Leads, Dia 9mm, Lead Spacing 10mm"
  round 1.35 hole 0.9: 1(-5,0) 2(5,0)
  body extent -5.3,-2 5.3,2, height 11.5
FP-RLTI-1439_PTH_XFRMR_2IN20_1IN73-MFG [mm]
  rrect3% 2.9x2.9 hole 1.9 paste-1000 mask+0: 1(-21.628,8.89)
  round 2.9 hole 1.9 paste-1000 mask+0: 2(-21.628,3.81) 3(-21.628,-3.81) 4(-21.628,-8.89) 5(20.282,-8.89) 6(20.282,-3.81) 7(20.282,3.81) 8(20.282,8.89)
  round 3.25 hole 2.15 paste-1000 mask+0: 9(-0.216,23.241) 10(-7.404,23.241) 11(-7.404,-23.241) 12(-0.216,-23.241)
  silkscreen extent -28.54,-21.97 27.94,21.97, body extent -28.04,-24.97 28.04,24.97, height 0.25
FUSE_372 [mm] "LITTELFUSE"
  round 1.5 hole 1: 1(-2.54,0) 2(2.54,0)
  silkscreen extent -4.25,-4.25 4.25,4.25, body extent -4.25,-4.25 4.25,4.25, height 8
GBU [mm] "Comchip / Diodes Inc diode bridge"
  round 2 hole 1.5: 1(-7.62,0) 2(-2.54,0) 3(2.54,0) 4(7.62,0)
  silkscreen extent -11.15,-2.28 11.15,1.28, body extent -11.15,-2.28 11.15,1.28, height 21.55
HSINK_634-10ABP [mil] "Wakefield"
  round 165 hole 116: MH1(-200,0) MH2(200,0)
  silkscreen extent -320,-135 320,502, body extent -320,-135 320,505, height 1000
IND_7447020 [mm] "WURTH ELEKTRONIK"
  round 1.25 hole 0.75: 1(-3.5,0) 2(3.5,0)
  silkscreen extent -3.8,-7.9 3.8,7.9, body extent -3.8,-7.84 3.75,7.9, height 15.78
IND_WE-CMB-S [mil] "Inductor, WE CMB Series Size S"
  rect 70x70 hole 40: 1(-98.43,-151.57)
  round 70 hole 40: 2(98.43,-151.57) 3(98.43,151.57) 4(-98.43,151.57)
  silkscreen extent -256,-346 256,344, body extent -256,-290 256,288, height 788
IND_WE-CMB_L [mm] "Wurth"
  round 2.3 hole 1.321: 2(-5,6) 4(5,6) 7(5,-6) 9(-5,-6)
  silkscreen extent -13.75,-9.25 13.75,9.25, body extent -13.75,-9.25 13.75,9.25, height 33.02
Keystone5001 [mil] "For Keystone 500x miniature loop terminals"
  round 80 hole 40: 1(0,0)
  silkscreen extent -52,-52 52,52, body extent -49,-49 49,49, height 182
Keystone5003 [mil] "For Keystone 500x miniature loop terminals"
  round 80 hole 40: 1(0,0)
  silkscreen extent -52,-52 52,52, body extent -49,-49 49,49, height 182
Keystone5010 [mil] "Keystone Multipurpose loops"
  round 87 hole 63: 1(0,0)
  silkscreen extent -70,-70 70,70, body extent -63,-63 63,62, height 319
Keystone5011 [mil] "Keystone Multipurpose loops"
  round 87 hole 63: 1(0,0)
  silkscreen extent -70,-70 70,70, body extent -63,-63 63,62, height 319
MPK_1800x950 [mm] "TH, 2-Leads, Body 18x9.5mm, Lead Spacing 15mm"
  round 1.55 hole 1.05: 1(-7.5,0) 2(7.5,0)
  silkscreen extent -9,-4.75 9,4.75, body extent -9,-4.75 9,4.75, height 14
Net-Tie_10mil [mil] "10mil net tie, no solder mask opening, no solder paste"
  rect 10x10 smd paste-5 mask-5: 1(-10,0) 2(10,0)
  Top Layer region: -6,5 6,5 6,-5 -6,-5
NHG_500x1100 [mm] "TH, 2-Leads, Dia 5mm,  Lead Spacing 2mm"
  rect 1.35x1.35 hole 0.85: 1(-1,0)
  round 1.35 hole 0.85: 2(1,0)
  silkscreen extent -2.75,-2.75 2.75,2.75, body extent -2.73,-2.75 2.75,2.75, height 12.51
On-Shore_ED120_2DS [mm] "ONSHORE"
  rrect5% 2x2 hole 1.25: 1(-2.54,0)
  round 2 hole 1.25: 2(2.54,0)
  silkscreen extent -5.6,-4 5.12,5, body extent -5.78,-4 5.08,5, height 13
RTW0024B [mm] "QFN, 24-Leads, Body 4x4mm, Pitch 0.5mm, Thermal Pad 2.45x2.45mm, TI Recommended"
  rrect42% 0.6x0.24 smd: 1(-1.9,1.25) 2(-1.9,0.75) 3(-1.9,0.25) 4(-1.9,-0.25) 5(-1.9,-0.75) 6(-1.9,-1.25) 13(1.9,-1.25) 14(1.9,-0.75) 15(1.9,-0.25) 16(1.9,0.25) 17(1.9,0.75) 18(1.9,1.25)
  rrect42% 0.24x0.6 smd: 7(-1.25,-1.9) 8(-0.75,-1.9) 9(-0.25,-1.9) 10(0.25,-1.9) 11(0.75,-1.9) 12(1.25,-1.9) 19(1.25,1.9) 20(0.75,1.9) 21(0.25,1.9) 22(-0.25,1.9) 23(-0.75,1.9) 24(-1.25,1.9)
  rrect4% 2.45x2.45 smd paste-1.225: 25(0,0)
  silkscreen extent -2.22,-2.22 2.22,2.22, body extent -2.07,-2.07 2.07,2.07, height 0.81
SMAF [mm] "SMD, 2-Leads, Body 3.8x2.5mm"
  rect 1.24x1.89 smd: 1(-2.04,0) 2(2.04,0)
  silkscreen extent -3.4,-1.3 2.8,1.3, body extent -2.35,-1.25 2.35,1.25, height 1
SMC [mil] "Molded Diode, 2-Leads, Body 6.9x5.8mm, IPC Medium Density, based on OnSemi component dimensions and land patterns"
  rect 110x150 smd: 1(-140.49,0) 2(140.49,0)
  silkscreen extent -221,-123 189,124, body extent -156,-116 156,116, height 91
SMQ_2540x2500 [mm] "United Chemi-Con"
  rect 3x3 hole 2: 1(-5,0)
  round 3 hole 2: 2(5,0)
  silkscreen extent -13.23,-13.24 13.24,13.24, body extent -13.1,-13.18 13.16,13.18, height 27.01
SOD-123 [mm] "On Semi recommended land pattern"
  rect 0.915x1.22 smd: 1(-1.637,0) 2(1.637,0)
  silkscreen extent -2.74,-1.17 2.03,1.17, body extent -1.93,-0.9 1.93,0.9, height 1.35
SOD-123FL [mm] "Copied from SOD-123"
  rect 0.915x1.22 smd: 1(-1.637,0) 2(1.637,0)
  silkscreen extent -2.74,-1.16 1.68,1.16, body extent -1.9,-0.9 1.9,0.9, height 1
SOD-123H [mm] "SMT, 2-Leads, Body 3.5x1.6mm"
  rect 1.3x1.8 smd: 1(-1.5,0) 2(1.5,0)
  silkscreen extent -2.9,-1.3 2.3,1.3, body extent -1.9,-0.9 1.9,0.9, height 1
SOD-323 [mm] "NXP recommended land pattern"
  rect 0.6x0.6 smd paste-0.05: 1(-1.1,0) 2(1.1,0)
  silkscreen extent -2.06,-0.86 1.53,0.86, body extent -1.3,-0.67 1.3,0.68, height 1.1
SOD-323-Bi [mm] "SOD323, 2-Leads, Body 1.9x1.45mm, No Polarity Mark"
  rect 0.6x0.6 smd paste-0.05: 1(-1.1,0) 2(1.1,0)
  silkscreen extent -1.53,-0.77 1.53,0.77, body extent -1.27,-0.65 1.27,0.65, height 1.02
SOD-523F [mm] "COMCHIP"
  rect 0.6x0.8 smd paste-0.05: 1(-0.85,0) 2(0.85,0)
  silkscreen extent -1.93,-0.88 1.1,0.87, body extent -0.9,-0.5 0.9,0.5, height 0.85
SOP254P1020X230-4 [mm] "VISHAY"
  rect 1.3x0.9 smd: 1(-4.75,1.27) 2(-4.75,-1.27) 3(4.75,-1.27) 4(4.75,1.27)
  body extent -3.85,-2.05 3.85,2.05, height 2.02
SOT-23 [mm] "SOT23, 3-Leads, Body 2.9x1.3mm, Pitch 0.95mm, Lead Span 2.5mm, IPC Medium Density"
  rrect50% 1x0.6 smd: 1(-1.2,0.95) 2(-1.2,-0.95) 3(1.2,0)
  silkscreen extent -1.63,-1.5 0.7,1.5, body extent -1.16,-1.45 1.21,1.45, height 1
SOT-223 [mm] "SOT223/SC73, 4-Leads, Body 6.5x3.5mm, Pitch 2.3mm, Lead Span 7mm, IPC Medium Density"
  rrect10% 2.4x1 smd: 1(-2.9,2.3) 2(-2.9,0) 3(-2.9,-2.3)
  rrect4% 2.4x3.3 smd: 4(2.9,0)
  silkscreen extent -3.32,-3.35 1.4,3.35, body extent -3.5,-3.25 3.5,3.25, height 1.62
SOT-323 [mm] "Diodes Inc recommended land pattern.  2016-02-24"
  rrect21% 0.6x0.47 smd: 1(-0.95,0.65) 2(-0.95,-0.65) 3(0.95,0)
  silkscreen extent -1.14,-1.22 0.77,1.22, body extent -1.13,-1.13 1.12,1.12, height 1.13
SOT-523 [mm] "From Diodes Inc datasheet component parameters"
  rect 0.9x0.4 smd: 1(-0.8,0.5) 2(-0.8,-0.5) 3(0.8,0)
  silkscreen extent 0.02,-0.85 0.42,0.85, body extent -0.8,-0.8 0.8,0.8, height 0.79
TESTPOINT_PIGTAIL [mil] "Pigtail"
  round 60 hole 42: 1(0,0)
  round 46 hole 32: 2(0,-200)
  silkscreen extent -50,-233 50,50
TNPW0603 [mm] "Vishay"
  rect 0.5x0.9 smd: 1(-0.75,0) 2(0.75,0)
  silkscreen extent -0.2,-0.6 0.2,0.6, body extent -0.85,-0.47 0.85,0.47, height 0.55
TO-220-3 [mm] "TH, 3-Leads, Body 10.2235x4.3815mm, Pitch 2.54mm"
  rrect50% 1.6x1.6 hole 1.1: 1(-2.54,0)
  round 1.6 hole 1.1: 2(0,0) 3(2.54,0)
  silkscreen extent -5.3,-1.7 5.3,2.9, body extent -5.27,-1.7 5.28,2.9, height 22.15
TO-220AB [mm] "Copied from Altium's version of TO3B"
  rrect25% 1.93x3 hole 1.27: 1(-2.54,0)
  oval 1.93x3 hole 1.27: 2(0,-3.81) 3(2.54,0)
  silkscreen extent -5.61,-1.49 5.61,3.2, body extent -5.61,-1.49 5.61,3.2, height 19.42
TO-220AC [mm]
  rrect50% 1.9x1.9 hole 1.4: 1(-2.54,0)
  round 1.9 hole 1.4: 3(2.54,0)
  silkscreen extent -5.25,-1.64 5.26,3.01, body extent -5.25,-1.64 5.26,3.01, height 19.09
VAR_S10K275E2 [mm] "EPCOS"
  round 1.6 hole 1.1: 1(-5.528,1.1) 2(5.528,-1.1)
  silkscreen extent -6,-2.7 6,2.7, body extent -5.98,-2.7 5.98,2.7, height 14.99
WCAP-FTX2_1300x700x1200 [mm] "TH, 2-Leads, Body 13x7mm, Pin Spacing 10mm"
  round 1.4 hole 0.9: 1(-5,0) 2(5,0)
  silkscreen extent -6.5,-3.5 6.5,3.5, body extent -6.5,-3.5 6.5,3.5, height 12.05
WCAP-FTX2_1500x1000x1600 [mm] "TH, 2-Leads, Body 15x10mm, Pin Spacing 12.5mm"
  round 1.4 hole 0.9: 1(-6.25,0) 2(6.25,0)
  silkscreen extent -7.52,-5 7.48,5, body extent -7.5,-5 7.5,5, height 16

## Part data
C1: library part ESMQ451VSN151MQ25S, "CAP, AL, 150 µF, 450 V, +/- 20%, TH", Cap_Case=25.4x25mm, Manufacturer=Rubycon, Tolerance_%=20, Value2=450V, ValueDisplayed=150µF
